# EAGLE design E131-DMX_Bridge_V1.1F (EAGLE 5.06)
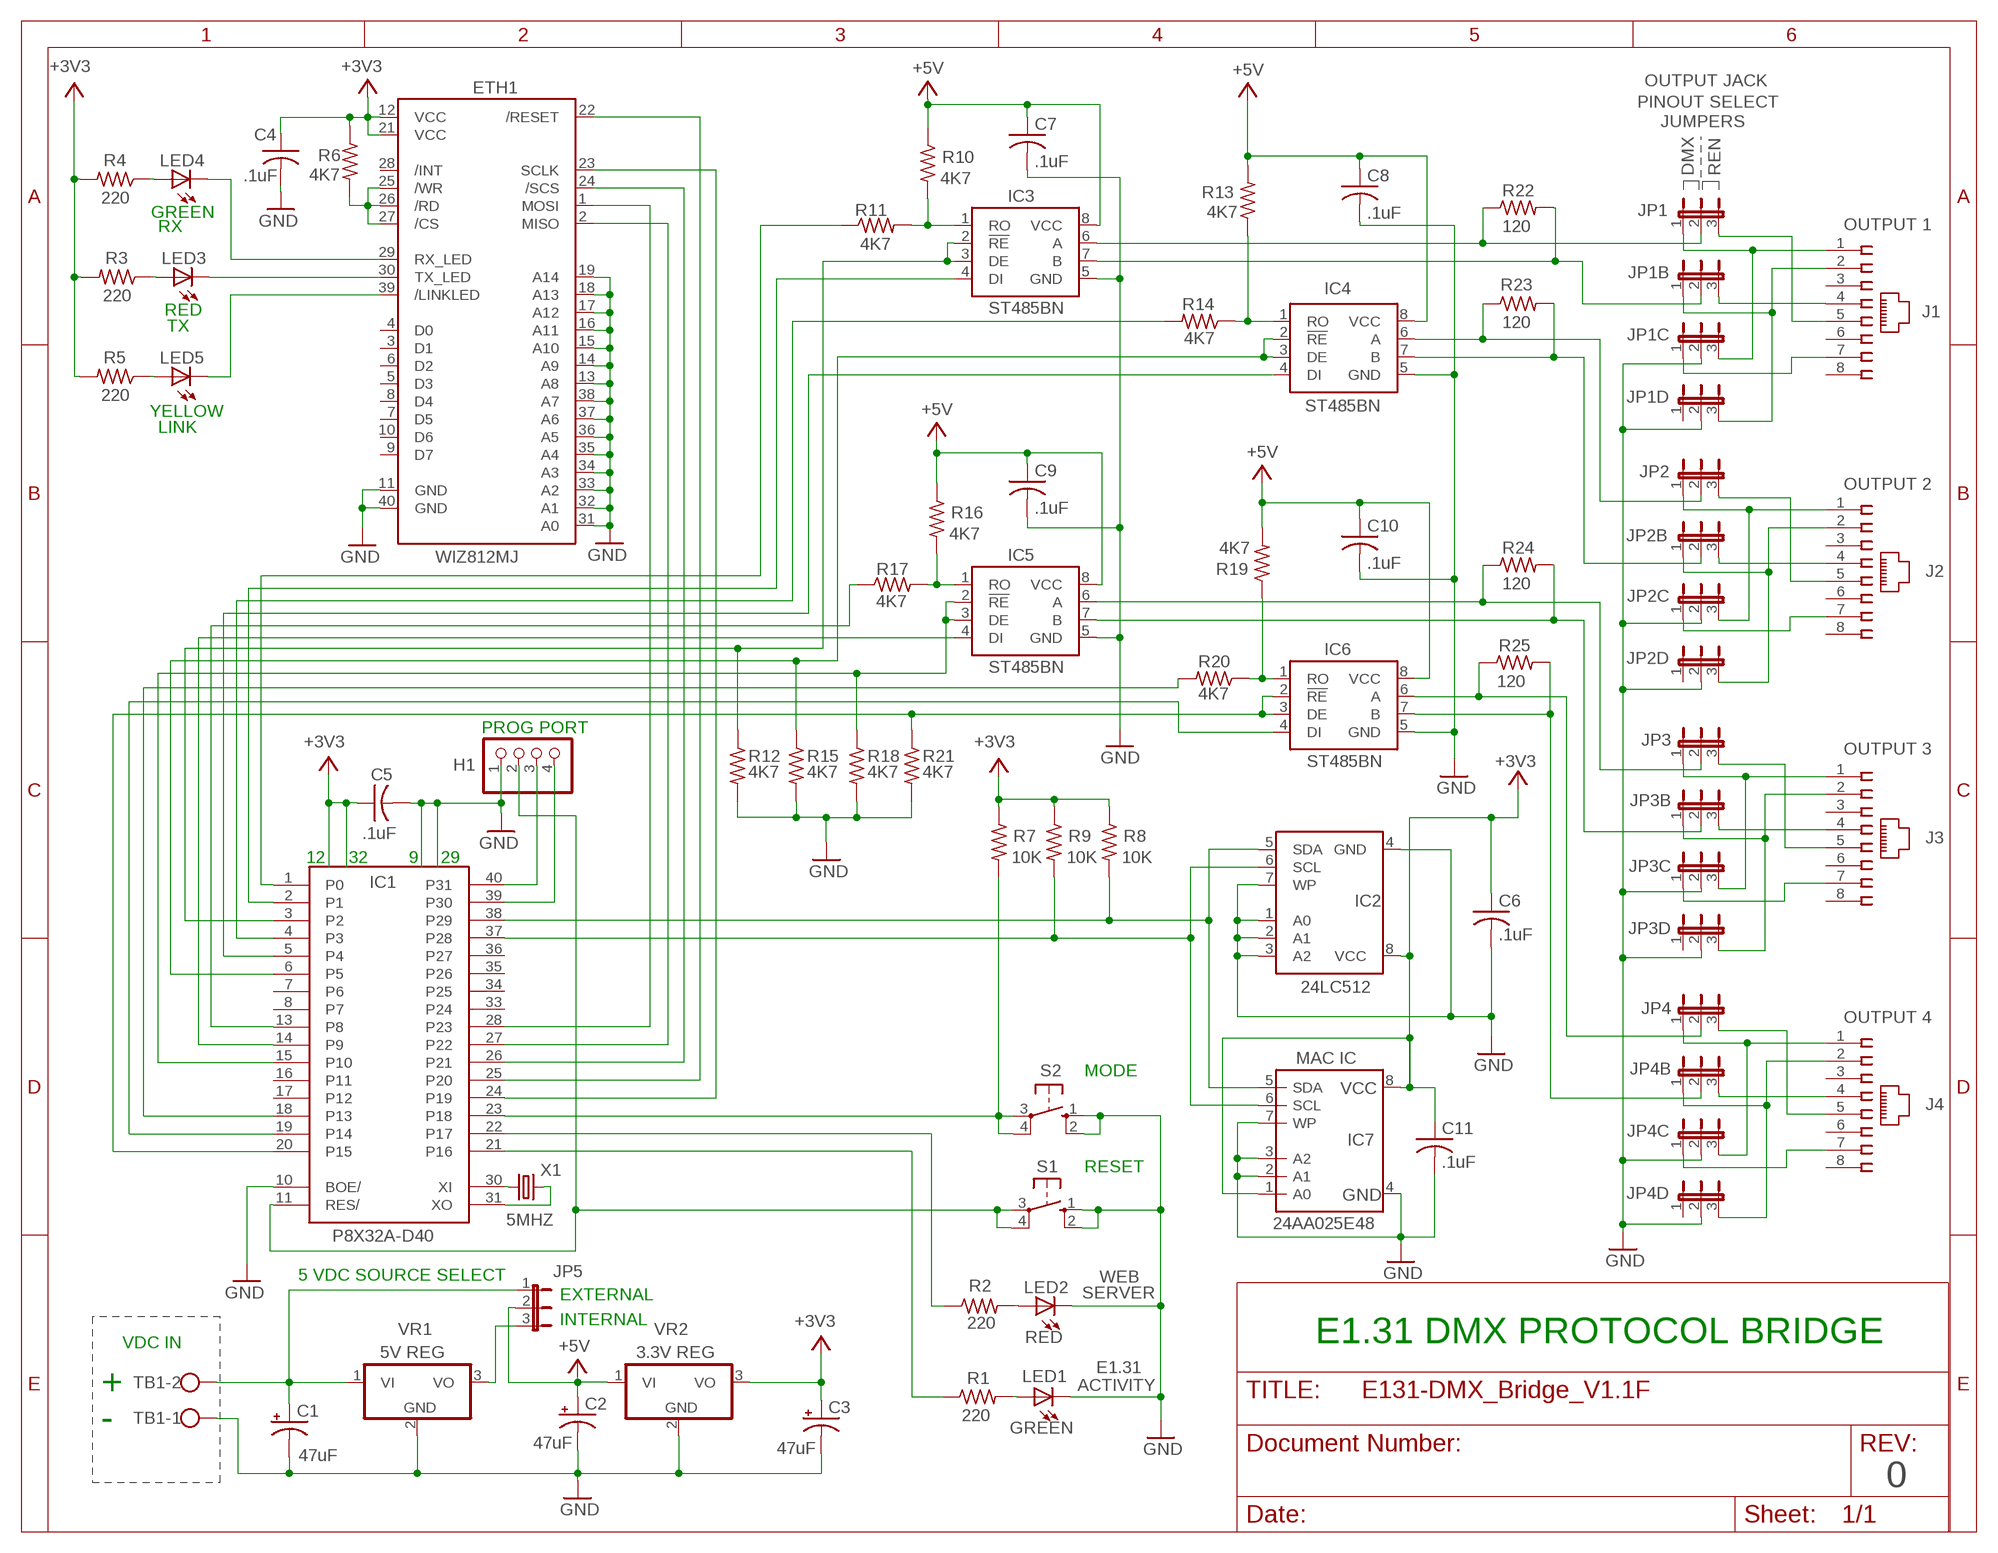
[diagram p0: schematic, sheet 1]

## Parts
C1  47uF  CPOL-USE2.5-6  [E2,5-6]
C2  47uF  CPOL-USE2.5-6  [E2,5-6]
C3  47uF  CPOL-USE2.5-6  [E2,5-6]
C4  .1uF  C-US075-032X103  [C075-032X103]
C5  .1uF  C-US075-032X103  [C075-032X103]
C6  .1uF  C-US075-032X103  [C075-032X103]
C7  .1uF  C-US075-032X103  [C075-032X103]
C8  .1uF  C-US075-032X103  [C075-032X103]
C9  .1uF  C-US075-032X103  [C075-032X103]
C10  .1uF  C-US075-032X103  [C075-032X103]
C11  .1uF  C-US075-032X103  [C075-032X103]
ETH1  WIZ812MJ  WIZ811MJ  [WIZ812MJ]
H1  PINHD-1X4  [1X04]
IC1  P8X32A-D40  [P8X32A-D40]
IC2  24LC512  AT24CP  [DIL08]
IC3  ST485BN  LTC485N  [DIL08]
IC4  ST485BN  LTC485N  [DIL08]
IC5  ST485BN  LTC485N  [DIL08]
IC6  ST485BN  LTC485N  [DIL08]
IC7  24AA025E48  24C04SN  [SO-08]
J1  520251-4  [520251-4]
J2  520251-4  [520251-4]
J3  520251-4  [520251-4]
J4  520251-4  [520251-4]
JP1  JP2E  [JP2]
JP1B  JP2E  [JP2]
JP1C  JP2E  [JP2]
JP1D  JP2E  [JP2]
JP2  JP2E  [JP2]
JP2B  JP2E  [JP2]
JP2C  JP2E  [JP2]
JP2D  JP2E  [JP2]
JP3  JP2E  [JP2]
JP3B  JP2E  [JP2]
JP3C  JP2E  [JP2]
JP3D  JP2E  [JP2]
JP4  JP2E  [JP2]
JP4B  JP2E  [JP2]
JP4C  JP2E  [JP2]
JP4D  JP2E  [JP2]
JP5  JP2E  [JP2]
LED1  LED5MM  [LED5MM]
LED2  LED5MM  [LED5MM]
LED3  LED5MM  [LED5MM]
LED4  LED5MM  [LED5MM]
LED5  LED5MM  [LED5MM]
R1  220  R-US_0207/10  [0207/10]
R2  220  R-US_0207/10  [0207/10]
R3  220  R-US_0207/10  [0207/10]
R4  220  R-US_0207/10  [0207/10]
R5  220  R-US_0207/10  [0207/10]
R6  4K7  R-US_0207/10  [0207/10]
R7  10K  R-US_0207/10  [0207/10]
R8  10K  R-US_0207/10  [0207/10]
R9  10K  R-US_0207/10  [0207/10]
R10  4K7  R-US_0207/10  [0207/10]
R11  4K7  R-US_0207/10  [0207/10]
R12  4K7  R-US_0207/10  [0207/10]
R13  4K7  R-US_0207/10  [0207/10]
R14  4K7  R-US_0207/10  [0207/10]
R15  4K7  R-US_0207/10  [0207/10]
R16  4K7  R-US_0207/10  [0207/10]
R17  4K7  R-US_0207/10  [0207/10]
R18  4K7  R-US_0207/10  [0207/10]
R19  4K7  R-US_0207/10  [0207/10]
R20  4K7  R-US_0207/10  [0207/10]
R21  4K7  R-US_0207/10  [0207/10]
R22  120  R-US_0207/10  [0207/10]
R23  120  R-US_0207/10  [0207/10]
R24  120  R-US_0207/10  [0207/10]
R25  120  R-US_0207/10  [0207/10]
S1  10-XX  [B3F-10XX]
S2  10-XX  [B3F-10XX]
TB1  W237-02P  [W237-132]
VR1  5V REG  7805T  [TO220H]
VR2  3.3V REG  7805T  [TO220H]
X1  5MHZ  CRYSTALHC49S  [HC49/S]

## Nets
+3V3: C3.+ C4.1 C5.1 C6.1 C11.1 ETH1.12(VCC) ETH1.21(VCC) IC2.8(VCC) IC7.1(A0) IC7.8(VCC) R3.2 R4.2 R5.2 R6.1 R7.1 R8.1 R9.1 VR2.3(VO)
+5V: C2.+ C7.1 C8.1 C9.1 C10.1 IC3.8(VCC) IC4.8(VCC) IC5.8(VCC) IC6.8(VCC) JP5.2 R10.1 R13.2 R16.1 R19.2 VR2.1(VI)
GND: C1.- C2.- C3.- C4.2 C5.2 C6.2 C7.2 C8.2 C9.2 C10.2 C11.2 ETH1.11(GND) ETH1.13(A8) ETH1.14(A9) ETH1.15(A10) ETH1.16(A11) ETH1.17(A12) ETH1.18(A13) ETH1.19(A14) ETH1.31(A0) ETH1.32(A1) ETH1.33(A2) ETH1.34(A3) ETH1.35(A4) ETH1.36(A5) ETH1.37(A6) ETH1.38(A7) ETH1.40(GND) H1.1 IC1.10(BOE/) IC2.1(A0) IC2.2(A1) IC2.3(A2) IC2.4(GND) IC2.7(WP) IC3.5(GND) IC4.5(GND) IC5.5(GND) IC6.5(GND) IC7.2(A1) IC7.3(A2) IC7.4(GND) IC7.7(WP) JP1C.2 JP1D.2 JP2C.2 JP2D.2 JP3C.2 JP3D.2 JP4C.2 JP4D.2 LED1.K(C) LED2.K(C) R12.2 R15.2 R18.2 R21.2 S1.1(S) S1.2(S1) S2.1(S) S2.2(S1) TB1.1 VR1.2(GND) VR2.2(GND)
N$1: IC5.1(RO) R16.2 R17.2
N$2: IC6.1(RO) R19.1 R20.1
N$3: IC4.1(RO) R13.1 R14.1
N$4: IC3.1(RO) R10.2 R11.2
N$5: ETH1.22(/RESET) IC1.25(P20)
N$6: ETH1.25(/WR) ETH1.26(/RD) ETH1.27(/CS) R6.2
N$7: ETH1.39(/LINKLED) LED5.K(C)
N$8: ETH1.1(MOSI) IC1.28(P23)
N$9: ETH1.2(MISO) IC1.27(P22)
N$10: ETH1.24(/SCS) IC1.26(P21)
N$11: ETH1.23(SCLK) IC1.24(P19)
N$12: IC1.1(P0) R11.1
N$13: IC1.2(P1) IC3.4(DI)
N$14: IC1.4(P3) R14.2
N$15: IC1.5(P4) IC4.4(DI)
N$16: IC1.30(XI) X1.1
N$17: IC1.31(XO) X1.2
N$18: IC1.21(P16) R1.1
N$19: LED1.A R1.2
N$20: IC1.22(P17) R2.1
N$21: LED2.A R2.2
N$22: C1.+ JP5.1 TB1.2 VR1.1(VI)
N$23: IC1.13(P8) R17.1
N$24: IC1.14(P9) IC5.4(DI)
N$25: IC1.18(P13) R20.2
N$26: IC1.19(P14) IC6.4(DI)
N$27: IC1.23(P18) R7.2 S2.3(P) S2.4(P1)
N$28: H1.3 IC1.40(P31)
N$29: H1.4 IC1.39(P30)
N$30: H1.2 IC1.11(RES/) S1.3(P) S1.4(P1)
N$31: IC1.38(P29) IC2.5(SDA) IC7.5(SDA) R8.2
N$32: IC1.37(P28) IC2.6(SCL) IC7.6(SCL) R9.2
N$33: J1.5 JP1.3
N$34: LED4.A R4.1
N$35: LED3.A R3.1
N$36: ETH1.29(RX_LED) LED4.K(C)
N$37: ETH1.30(TX_LED) LED3.K(C)
N$38: IC1.20(P15) IC6.2(!RE) IC6.3(DE) R21.1
N$39: IC1.6(P5) IC4.2(!RE) IC4.3(DE) R15.1
N$40: J1.2 JP1B.1 JP1D.3
N$41: IC3.6(A) JP1.2 R22.1
N$42: IC3.7(B) JP1B.2 R22.2
N$43: J1.7 JP1C.1
N$44: J4.5 JP4.3
N$45: J2.2 JP2B.1 JP2D.3
N$46: J2.7 JP2C.1
N$47: IC5.6(A) JP3.2 R24.1
N$48: IC5.7(B) JP3B.2 R24.2
N$49: J3.5 JP3.3
N$50: J3.2 JP3B.1 JP3D.3
N$51: J3.7 JP3C.1
N$52: J2.5 JP2.3
N$53: IC6.6(A) JP4.2 R25.1
N$54: LED5.A R5.1
N$55: IC6.7(B) JP4B.2 R25.2
N$56: J4.2 JP4B.1 JP4D.3
N$57: J4.7 JP4C.1
N$58: J1.1 JP1.1 JP1C.3
N$59: J1.4 JP1B.3
N$60: IC4.6(A) JP2.2 R23.1
N$61: IC1.15(P10) IC5.2(!RE) IC5.3(DE) R18.1
N$62: IC4.7(B) JP2B.2 R23.2
N$63: IC1.3(P2) IC3.2(!RE) IC3.3(DE) R12.1
N$64: J2.4 JP2B.3
N$65: J2.1 JP2.1 JP2C.3
N$66: J3.4 JP3B.3
N$67: J3.1 JP3.1 JP3C.3
N$68: J4.4 JP4B.3
N$69: J4.1 JP4.1 JP4C.3
N$70: JP5.3 VR1.3(VO)
Unconnected: ETH1.3(D1) ETH1.4(D0) ETH1.5(D3) ETH1.6(D2) ETH1.7(D5) ETH1.8(D4) ETH1.9(D7) ETH1.10(D6) ETH1.28(/INT) IC1.7(P6) IC1.8(P7) IC1.16(P11) IC1.17(P12) IC1.33(P24) IC1.34(P25) IC1.35(P26) IC1.36(P27) J1.3 J1.6 J1.8 J2.3 J2.6 J2.8 J3.3 J3.6 J3.8 J4.3 J4.6 J4.8 JP1D.1 JP2D.1 JP3D.1 JP4D.1

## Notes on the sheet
- OUTPUT JACK
- PINOUT SELECT
- JUMPERS
- DMX | REN
- GREEN
- RX | OUTPUT 1
- RED
- TX
- YELLOW
- LINK
- OUTPUT 2
- PROG PORT
- OUTPUT 3
- 12 | 32
- 9 | 29
- OUTPUT 4
- MAC IC
- MODE
- RESET
- WEB
- 5 VDC SOURCE SELECT
- SERVER
- EXTERNAL
- INTERNAL
- RED
- E1.31 DMX PROTOCOL BRIDGE
- VDC IN
- E1.31
- ACTIVITY
- +
- GREEN
- -
- 0

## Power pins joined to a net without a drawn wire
+3V3: IC1.12(+3V3) IC1.32(+3V3)
GND: IC1.9(GND) IC1.29(GND)

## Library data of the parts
C1-C3 = rcl:CPOL-US: POLARIZED CAPACITOR, American symbol
C4-C11 = rcl:C-US: CAPACITOR, American symbol
ETH1 = SparkFun:WIZ811MJ: WIZnet W5100 Network Module with MagJack - WIZ811MJ WIZnet's WIZ811MJ is a breakout board for the W5100 embedded TCP/IP chip. Also included on the board is a RJ-45 MagJack Connector (RJ45 with X'FMR). See http://www.sparkfun.com/commerce/product_info.php?products_id=9473 for more documentation and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
H1 = pinhead:PINHD-1X4: PIN HEADER
IC1 = parallax_propeller:P8X32A-D40
IC2 = atmel:AT24C*: 2-wire serial EEPROM
IC3-IC6 = linear-technology:LTC485: Low Power RS485 Interface Transceiver Source: http://www.linear.com/pc/downloadDocument.do?navId=H0,C1,C1007,C1017,P2064,D1718
IC7 = microchip:24C*: Serial EEPROM 1 K/2 K/4 K
J1-J4 = con-amp:520251-4: AMP connector
JP1 JP1B JP1C JP1D JP2 JP2B JP2C JP2D JP3 JP3B JP3C JP3D JP4 JP4B JP4C JP4D JP5 = jumper:JP2E: JUMPER
LED1-LED5 = led:LED: LED
R1-R25 = rcl:R-US_: RESISTOR, American symbol
S1 S2 = switch-omron:10-XX: OMRON SWITCH
TB1 = con-wago-508:W237-02P: WAGO SREW CLAMP
VR1 VR2 = linear:78*: Positive VOLTAGE REGULATOR Source: http://cache.national.com/ds/LM/LM78L05.pdf http://www.fairchildsemi.com/ds/LM/LM7805.pdf
X1 = crystal:CRYSTAL: CRYSTAL

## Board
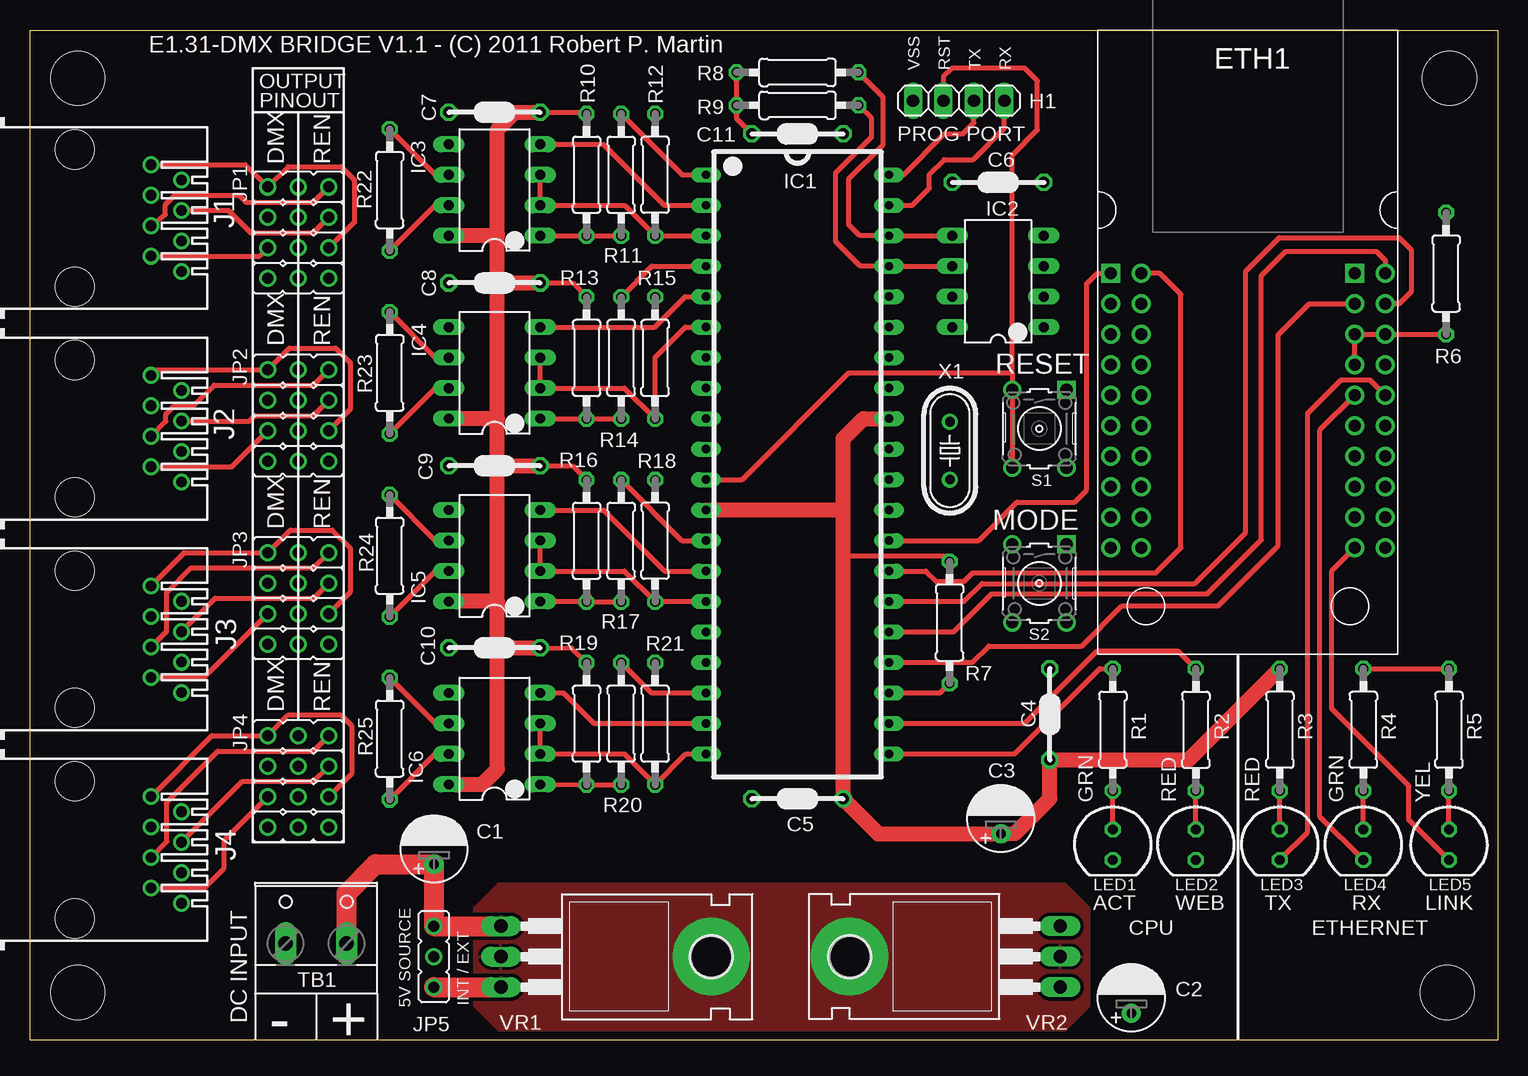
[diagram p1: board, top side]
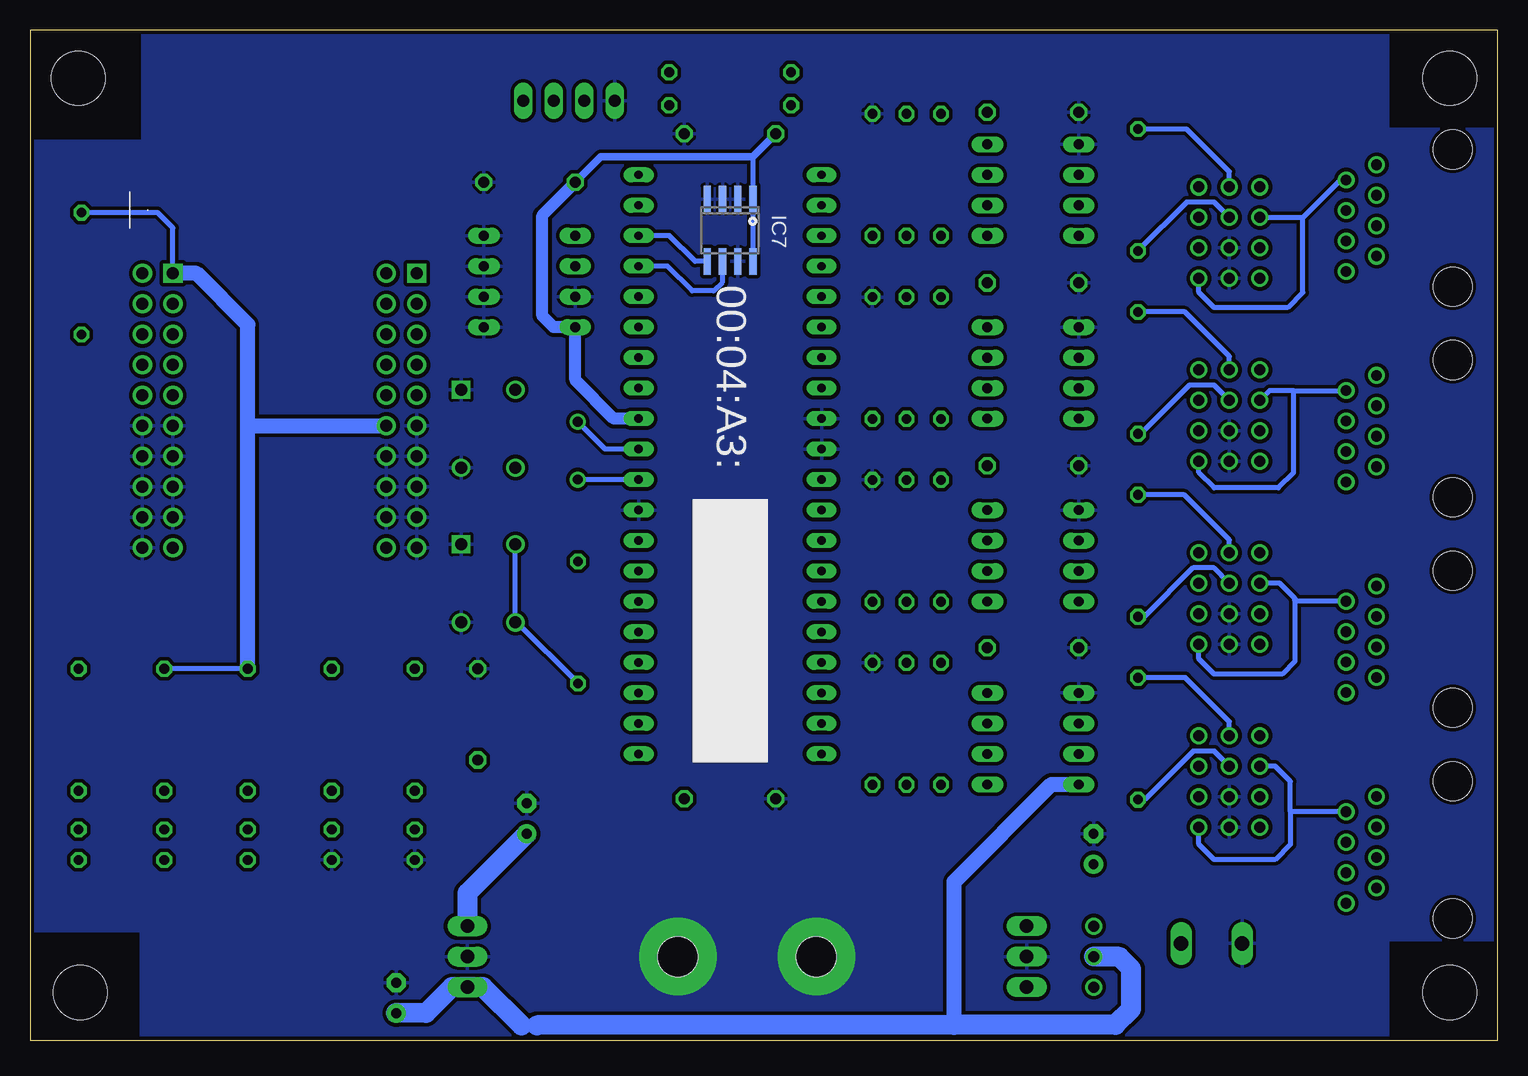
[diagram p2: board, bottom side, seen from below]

Size 122.3 x 84.2 mm. Coordinates in mm from the lower left corner, seen from the top.
Copper layers (1+16): Top 0.035mm / dielectric 1.5mm / Bottom 0.035mm
Design rules "default *": minimum track width 8mil, minimum drill 24mil, track to track 10mil, track to pad 10mil, pad to pad 10mil, via to via 10mil, smd to smd 8mil, copper to edge 8mil, drill to drill 10mil, minimum pad ring 10mil, minimum via ring 8mil, stop-mask expansion 4mil, vias tented up to drill 0mil, thermal gap 10mil

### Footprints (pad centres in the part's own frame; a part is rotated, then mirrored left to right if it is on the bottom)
E2,5-6 = drill 0.813 pad 1.6 round: + -1.27,0 | drill 0.813 pad 1.6 octagon: - 1.27,0
C075-032X103 = drill 0.914 octagon: 1 -3.81,0; 2 3.81,0
WIZ812MJ = drill 1 pad 1.6 square: 1 -11.43,5.25; 21 8.89,5.25 | drill 1 pad 1.6 round: 2 -8.89,5.25; 3 -11.43,2.71; 4 -8.89,2.71; 5 -11.43,0.17; 6 -8.89,0.17; 7 -11.43,-2.37; 8 -8.89,-2.37; 9 -11.43,-4.91; 10 -8.89,-4.91; 11 -11.43,-7.45; 12 -8.89,-7.45; 13 -11.43,-9.99; 14 -8.89,-9.99; 15 -11.43,-12.53; 16 -8.89,-12.53; 17 -11.43,-15.07; 18 -8.89,-15.07; 19 -11.43,-17.61; 20 -8.89,-17.61; 22 11.43,5.25; 23 8.89,2.71; 24 11.43,2.71; 25 8.89,0.17; 26 11.43,0.17; 27 8.89,-2.37; 28 11.43,-2.37; 29 8.89,-4.91; 30 11.43,-4.91; 31 8.89,-7.45; 32 11.43,-7.45; 33 8.89,-9.99; 34 11.43,-9.99; 35 8.89,-12.53; 36 11.43,-12.53; 37 8.89,-15.07; 38 11.43,-15.07; 39 8.89,-17.61; 40 11.43,-17.61
1X04 = drill 1.016 long: 1 -3.81,0; 2 -1.27,0; 3 1.27,0; 4 3.81,0
P8X32A-D40 = drill 0.7 pad 1.27 long: 1 -7.62,23.495; 2 -7.62,20.955; 3 -7.62,18.415; 4 -7.62,15.875; 5 -7.62,13.335; 6 -7.62,10.795; 7 -7.62,8.255; 8 -7.62,5.715; 9 -7.62,3.175; 10 -7.62,0.635; 11 -7.62,-1.905; 12 -7.62,-4.445; 13 -7.62,-6.985; 14 -7.62,-9.525; 15 -7.62,-12.065; 16 -7.62,-14.605; 17 -7.62,-17.145; 18 -7.62,-19.685; 19 -7.62,-22.225; 20 -7.62,-24.765; 21 7.62,-24.765; 22 7.62,-22.225; 23 7.62,-19.685; 24 7.62,-17.145; 25 7.62,-14.605; 26 7.62,-12.065; 27 7.62,-9.525; 28 7.62,-6.985; 29 7.62,-4.445; 30 7.62,-1.905; 31 7.62,0.635; 32 7.62,3.175; 33 7.62,5.715; 34 7.62,8.255; 35 7.62,10.795; 36 7.62,13.335; 37 7.62,15.875; 38 7.62,18.415; 39 7.62,20.955; 40 7.62,23.495
DIL08 = drill 0.813 long: 1 -3.81,-3.81; 2 -1.27,-3.81; 3 1.27,-3.81; 4 3.81,-3.81; 5 3.81,3.81; 6 1.27,3.81; 7 -1.27,3.81; 8 -3.81,3.81
SO-08 = smd 0.6 x 2.2: 1 -1.905,-2.6; 2 -0.635,-2.6; 3 0.635,-2.6; 4 1.905,-2.6; 5 1.905,2.6; 6 0.635,2.6; 7 -0.635,2.6; 8 -1.905,2.6
520251-4 = drill 0.889 round: 1 -4.445,6.35; 2 -3.175,8.89; 3 -1.905,6.35; 4 -0.635,8.89; 5 0.635,6.35; 6 1.905,8.89; 7 3.175,6.35; 8 4.445,8.89 | hole 3.251: -5.715,0; 5.715,0
JP2 = drill 0.914 round: 1 -2.54,0; 2 0,0; 3 2.54,0
LED5MM = drill 0.813 octagon: A -1.27,0; K 1.27,0
0207/10 = drill 0.813 octagon: 1 -5.08,0; 2 5.08,0
B3F-10XX = drill 1.016 square: 1 -3.251,2.261 | drill 1.016 round: 2 3.251,2.261; 3 -3.251,-2.261; 4 3.251,-2.261
W237-132 = drill 1.194 long: 1 -2.54,-0.635; 2 2.54,-0.635
4.8X3.3 = hole 4.5: 3.988,3.988; 3.988,80.188; 118.288,80.188; 118.11,3.988
TO220H = drill 1.118 long: 1 -2.54,-12.7; 2 0,-12.7; 3 2.54,-12.7 | hole 3.302: 0,4.826
HC49/S = drill 0.813 round: 1 -2.413,0; 2 2.413,0

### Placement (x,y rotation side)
C1  33.67,15.95 90 top
C2  91.78,3.54 90 top
C3  80.91,18.49 90 top
C4  84.99,27.18 90 top
C5  63.96,20.13 180 top
C6  80.67,71.5 0 top
C7  38.71,77.34 180 top
C8  38.71,63.12 180 top
C9  38.71,47.88 180 top
C10  38.71,32.72 180 top
C11  63.96,75.54 0 top
ETH1  101.5,58.67 0 top
H1  77.39,78.31 0 top
IC1  63.96,48.64 0 top
IC2  80.67,63.25 90 top
IC3  38.71,70.87 90 top
IC4  38.71,55.63 90 top
IC5  38.71,40.39 90 top
IC6  38.71,25.15 90 top
IC7  63.96,67.51 180 bottom
J1  3.73,68.53 270 top
J2  3.73,50.98 270 top
J3  3.73,33.43 270 top
J4  3.73,15.88 270 top
JP1  22.35,71.12 0 top
JP1B  22.35,68.58 0 top
JP1C  22.35,66.04 0 top
JP1D  22.35,63.5 0 top
JP2  22.35,55.88 0 top
JP2B  22.35,53.34 0 top
JP2C  22.35,50.8 0 top
JP2D  22.35,48.26 0 top
JP3  22.35,40.64 0 top
JP3B  22.35,38.1 0 top
JP3C  22.35,35.56 0 top
JP3D  22.35,33.02 0 top
JP4  22.35,25.4 0 top
JP4B  22.35,22.86 0 top
JP4C  22.35,20.32 0 top
JP4D  22.35,17.78 0 top
JP5  33.66,6.99 270 top
LED1  90.23,16.31 270 top
LED2  97.16,16.31 270 top
LED3  104.15,16.31 270 top
LED4  111.11,16.31 270 top
LED5  118.25,16.31 270 top
R1  90.23,25.9 270 top
R2  97.16,25.88 270 top
R3  104.15,25.88 90 top
R4  111.11,25.88 90 top
R5  118.25,25.88 90 top
R6  118.01,63.91 270 top
R7  76.63,34.82 270 top
R8  63.96,80.67 0 top
R9  63.96,77.93 0 top
R10  46.38,72.14 270 top
R11  49.26,72.14 270 top
R12  52.1,72.14 90 top
R13  46.38,56.87 90 top
R14  49.26,56.87 90 top
R15  52.1,56.87 90 top
R16  46.38,41.63 270 top
R17  49.26,41.63 270 top
R18  52.1,41.63 90 top
R19  46.38,26.39 90 top
R20  49.26,26.39 90 top
R21  52.1,26.39 90 top
R22  29.97,70.87 270 top
R23  29.97,55.63 270 top
R24  29.97,40.39 270 top
R25  29.97,25.15 270 top
S1  84.11,50.98 270 top
S2  84.11,38.09 270 top
TB1  23.84,8.71 0 top
U$1  [4.8X3.3]  0,0 0 top
VR1  51.94,6.99 270 top
VR2  73.15,6.99 90 top
X1  76.66,49.15 90 top

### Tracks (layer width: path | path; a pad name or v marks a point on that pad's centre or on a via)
+3V3
  Top 0.406: R4.2 R5.2 | R7.1 76.15,40.39 68.3,40.39 68.28,40.36 67.77,40.36 | R8.1 R9.1 58.88,76.81 C11.1
  Top 1.27: R3.2 96.56,23.37 C4.1 84.99,20.14 82.09,17.25 C3.+ 70.67,17.22 C5.1 67.77,40.36 67.77,43.97 | IC1.32 69.44,51.82 67.77,50.14 67.77,43.97 | IC1.12 67.77,44.2 67.77,43.97
  Bottom 0.406: R3.2 R4.2 | ETH1.21 110.39,67.72 111.66,68.99 R6.1 | IC7.8 IC7.1 62.05,73.46 62.23,73.64
  Bottom 0.61: C6.1 74.73,73.64 62.23,73.64 62.05,73.64 C11.1
  Bottom 1.016: C6.1 79.6,68.76 79.6,60.38 78.66,59.44 IC2.8 76.86,55.04 73.64,51.82 IC1.32
  Bottom 1.27: 104.15,51.22 ETH1.12 | R3.2 104.15,51.22 | 104.15,51.22 104.15,59.65 108.42,63.92 ETH1.21
  Bottom 1.676: VR2.3 85.85,12.28 C3.+
+5V
  Top 0.406: R19.2 45.16,32.69 C10.1 | R13.2 45.21,63.12 C8.1 | R16.1 45.21,47.88 C9.1 | C7.1 46.25,77.34 R10.1
  Top 1.27: 38.94,32.84 38.94,36.22 | 38.94,36.22 38.94,48.13 | 38.94,48.13 38.94,51.77 | 38.94,51.77 38.94,63.2 | 38.94,63.2 38.94,67.21 | C8.1 38.94,63.12 38.94,63.2 | C9.1 38.94,47.88 38.94,48.13 | C10.1 38.94,32.72 38.94,32.84 | IC5.8 38.94,36.58 38.94,36.22 | IC4.8 38.94,51.82 38.94,51.77 | IC3.8 38.94,67.06 38.94,67.21 | 38.94,67.21 38.94,75.89 40.39,77.34 C7.1 | 38.94,32.84 38.94,22.61 37.67,21.34 IC6.8
  Bottom 0.203: 81.33,1.25 80.64,1.27 80.06,1.25
  Bottom 1.27: IC6.8 37.19,21.34 45.29,13.23 45.29,1.29
  Bottom 1.676: 80.06,1.25 45.29,1.29 31.85,1.29 30.53,2.62 30.53,5.97 31.52,6.96 JP5.2 | 81.33,1.25 84.53,4.45 VR2.1 87.15,4.45 89.29,2.3 C2.+
GND  (via drill 3.2 pad 6.45)
  other vias: 56.77,6.99 68.3,6.99
  pour Top (isolate 0.305): 86.24,13.06 88.24,11.06 88.24,2.86 86.24,0.86 39.06,0.86 37.06,2.86 37.06,11.06 39.06,13.06
  pour Bottom (isolate 0.305): 0.25,75.95 9.14,75.95 9.14,83.82 112.9,83.82 112.9,74.93 121.92,74.93 121.92,9.14 113.03,9.14 113.03,0.25 9.14,0.25 9.14,8.38 0.25,8.38
N$1
  Top 0.406: R17.2 R16.2 46.35,36.58 IC5.1
N$2
  Top 0.406: R20.1 R19.1 IC6.1
N$3
  Top 0.406: R14.1 R13.1 46.35,51.82 IC4.1
N$4
  Top 0.406: R11.2 R10.2 IC3.1
N$5
  Top 0.406: ETH1.22 112.93,65.02 112.19,65.76 104.65,65.76 102.62,63.73 102.62,41.71 98.12,37.21 80.14,37.21 76.96,34.04 IC1.25
N$6
  Top 0.406: ETH1.27 ETH1.25 ETH1.26 112.95,58.83 R6.2
N$7
  Top 0.406: LED5.K 114.91,18.38 114.91,21.21 108.48,27.64 108.48,39.16 ETH1.39
N$8
  Top 0.406: ETH1.1 88.92,63.92 88.06,63.07 88.06,45.86 87.06,44.86 82.25,44.86 79.05,41.66 IC1.28
N$9
  Top 0.406: ETH1.2 94.17,63.92 95.91,62.18 95.91,41.05 93.83,38.96 78.56,38.96 77.85,38.25 75.51,38.25 74.65,39.12 IC1.27
N$10
  Top 0.406: ETH1.24 114.09,61.38 115.09,62.38 115.09,65.9 114.09,66.9 104.11,66.9 101.3,64.08 101.3,42.32 97.05,38.08 79.32,38.08 77.83,36.58 IC1.26
N$11
  Top 0.406: ETH1.23 106.6,61.38 104.01,58.8 104.01,41.22 99.01,36.22 90.98,36.22 87.63,32.87 79.88,32.87 78.51,31.5 IC1.24
N$12
  Top 0.406: R11.1 54.34,72.14 IC1.1
N$13
  Top 0.406: IC3.4 47.78,74.68 52.86,69.6 IC1.2
N$14
  Top 0.406: R14.2 51.83,64.52 IC1.4
N$15
  Top 0.406: IC4.4 52.05,59.44 54.59,61.98 IC1.5
N$16
  Bottom 0.406: IC1.30 X1.1
N$17
  Bottom 0.406: X1.2 74.37,49.28 IC1.31
N$18
  Top 0.406: R1.1 89.14,30.98 82.04,23.88 IC1.21
N$19
  Top 0.406: LED1.A R1.2
N$20
  Top 0.406: R2.1 95.66,32.46 88.95,32.46 82.91,26.42 IC1.22
N$21
  Top 0.406: LED2.A R2.2
N$22
  Top 1.676: VR1.1 JP5.1 33.66,14.67 C1.+ 28.78,14.68 26.38,12.28 TB1.2
N$23
  Top 0.406: R17.1 54.32,41.66 IC1.13
N$24
  Top 0.406: IC5.4 47.83,44.2 52.91,39.12 IC1.14
N$25
  Top 0.406: R20.2 51.78,28.96 IC1.18
N$26
  Top 0.406: IC6.4 44.45,28.96 46.99,26.42 IC1.19
N$27
  Top 0.406: R7.2 75.84,28.96 IC1.23
  Bottom 0.406: S2.3 S2.4 81.72,34.84 R7.2
N$28
  Top 0.406: H1.3 78.66,76.45 77.75,75.54 76.2,75.54 72.8,72.14 IC1.40
N$29
  Top 0.406: H1.4 81.2,76.02 78.59,73.41 76.17,73.41 74.95,72.19 74.95,71.02 73.53,69.6 IC1.39
N$30
  Top 0.406: S1.4 S1.3 81.85,55.63 | IC1.11 59.33,46.74 68.22,55.63 81.85,55.63 | 81.85,55.63 81.85,73.77 83.95,75.87 83.95,79.96 82.88,81.03 76.83,81.03 76.12,80.31 H1.2
N$31
  Top 0.406: IC2.5 IC1.38 69.16,67.06 68.25,67.97 68.25,71.81 71.09,74.65 71.09,78.61 R8.2
  Bottom 0.406: IC7.5 66.87,64.91 69.01,67.06 IC1.38
N$32
  Top 0.406: IC2.6 IC1.37 69.19,64.52 67.13,66.57 67.13,72.29 70.13,75.29 70.13,76.83 R9.2
  Bottom 0.406: IC7.6 64.59,63.2 65.33,62.46 67.13,62.46 69.19,64.52 IC1.37
N$33
  Top 0.406: JP1.3 23.62,69.85 18.01,69.85 17.42,70.43 12.06,70.43 11.28,69.65 11.28,68.83 J1.5
N$34
  Top 0.406: LED4.A R4.1
N$35
  Top 0.406: LED3.A R3.1
N$36
  Top 0.406: LED4.K 107.49,18.66 107.49,50.87 ETH1.29
N$37
  Top 0.406: LED3.K 106.48,17.36 106.48,52.25 109.27,55.04 111.65,55.04 ETH1.30
N$38
  Top 0.406: IC6.3 IC6.2 49.53,23.88 R21.1 54.66,23.88 IC1.20
N$39
  Top 0.406: IC4.3 IC4.2 49.53,54.36 R15.1 52.09,56.92 54.61,59.44 IC1.6
N$40
  Bottom 0.406: JP1B.1 19.79,68.56 16.23,68.56 | JP1D.3 24.89,62.33 23.62,61.06 17.5,61.06 16.23,62.33 16.23,68.56 | 16.23,68.56 13.08,71.7 J1.2
N$41
  Top 0.406: R22.1 33.78,72.14 IC3.6
  Bottom 0.406: JP1.2 22.35,72.39 25.91,75.95 R22.1
N$42
  Top 0.406: R22.2 33.78,69.6 IC3.7
  Bottom 0.406: R22.2 25.91,69.85 23.62,69.85 JP1B.2
N$43
  Top 0.406: J1.7 19.13,65.35 JP1C.1
N$44
  Top 0.406: JP4.3 23.6,24.11 15.65,24.11 11.4,19.86 11.4,16.56 J4.5
N$45
  Bottom 0.406: JP2D.3 24.89,47.32 23.62,46.05 18.26,46.05 16.99,47.32 16.99,54.15 | 16.99,54.15 J2.2 | JP2B.1 19,54.15 16.99,54.15
N$46
  Top 0.406: J2.7 16.82,47.8 JP2C.1
N$47
  Top 0.406: IC5.6 33.78,41.66 R24.1
  Bottom 0.406: JP3.2 22.35,41.71 26.11,45.47 R24.1
N$48
  Top 0.406: IC5.7 33.78,39.12 R24.2
  Bottom 0.406: JP3B.2 23.62,39.37 25.4,39.37 29.46,35.31 R24.2
N$49
  Top 0.406: J3.5 11.38,34.09 11.38,37.31 13.44,39.37 23.62,39.37 JP3.3
N$50
  Bottom 0.406: JP3D.3 24.89,31.8 23.62,30.53 17.96,30.53 16.89,31.6 16.89,36.63 | 16.89,36.63 16.89,36.83 18.16,38.1 JP3B.1 | J3.2 16.87,36.6 16.89,36.63
N$51
  Top 0.406: J3.7 14.5,30.25 JP3C.1
N$52
  Top 0.406: JP2.3 23.62,54.61 15.34,54.61 13.61,52.88 12.04,52.88 11.33,52.17 11.33,51.59 J2.5
N$53
  Top 0.406: R25.1 33.78,26.42 IC6.6
  Bottom 0.406: JP4.2 22.35,26.57 26.01,30.23 R25.1
N$54
  Top 0.406: LED5.A R5.1
N$55
  Top 0.406: R25.2 33.78,23.88 IC6.7
  Bottom 0.406: JP4B.2 23.6,24.11 25.38,24.11 29.41,20.07 R25.2
N$56
  Bottom 0.406: 17.27,19.05 17.27,21.59 18.54,22.86 JP4B.1 | JP4D.3 24.89,16.33 23.62,15.06 18.54,15.06 17.27,16.33 17.27,19.05 | J4.2 17.27,19.05
N$57
  Top 0.406: JP4C.1 16.18,16.69 16.18,14.35 14.53,12.7 J4.7
N$58
  Top 0.406: JP1C.3 27.03,68.17 27.03,71.73 25.93,72.82 21.51,72.82 JP1.1 17.96,72.97 J1.1
N$59
  Top 0.406: JP1B.3 23.62,67.31 18.39,67.31 16.54,69.16 J1.4
N$60
  Top 0.406: R23.1 33.78,56.9 IC4.6
  Bottom 0.406: JP2.2 22.35,57 26.06,60.71 R23.1
N$61
  Top 0.406: IC5.3 IC5.2 49.53,39.12 R18.1 52.12,36.58 IC1.15
N$62
  Top 0.406: R23.2 33.78,54.36 IC4.7
  Bottom 0.406: JP2B.2 23.62,54.61 25.68,54.61 29.74,50.55 R23.2
N$63
  Top 0.406: IC3.3 IC3.2 49.55,69.6 R12.1 IC1.3
N$64
  Top 0.406: JP2B.3 23.62,52.07 18.72,52.07 18.26,51.61 J2.4
N$65
  Top 0.406: JP2C.3 26.7,52.6 26.7,56.46 25.48,57.68 21.61,57.68 JP2.1 10.54,55.88 J2.1
N$66
  Top 0.406: JP3B.3 23.65,36.85 15.42,36.85 J3.4
N$67
  Top 0.406: JP3C.3 26.67,37.34 26.67,41.05 25.2,42.52 21.69,42.52 JP3.1 12.85,40.64 J3.1
N$68
  Top 0.406: JP4B.3 23.62,21.59 17.7,21.59 J4.4
N$69
  Top 0.406: JP4C.3 26.8,22.23 26.8,26.21 25.88,27.13 21.54,27.13 JP4.1 15.16,25.4 J4.1
N$70
  Top 1.676: JP5.3 VR1.3

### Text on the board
tNames: E1.31-DMX BRIDGE V1.1 - (C) 2011 Robert P. Martin | VSS | RST | TX | RX | OUTPUT | PINOUT | PROG PORT | DMX | REN | DMX | REN | RESET | MODE | DMX | REN | DMX | REN | GRN | RED | RED | GRN | YEL | ACT | WEB | TX | RX | LINK | CPU | ETHERNET | 5V SOURCE | INT / EXT | DC INPUT | - | +
bNames: 00:04:A3:
